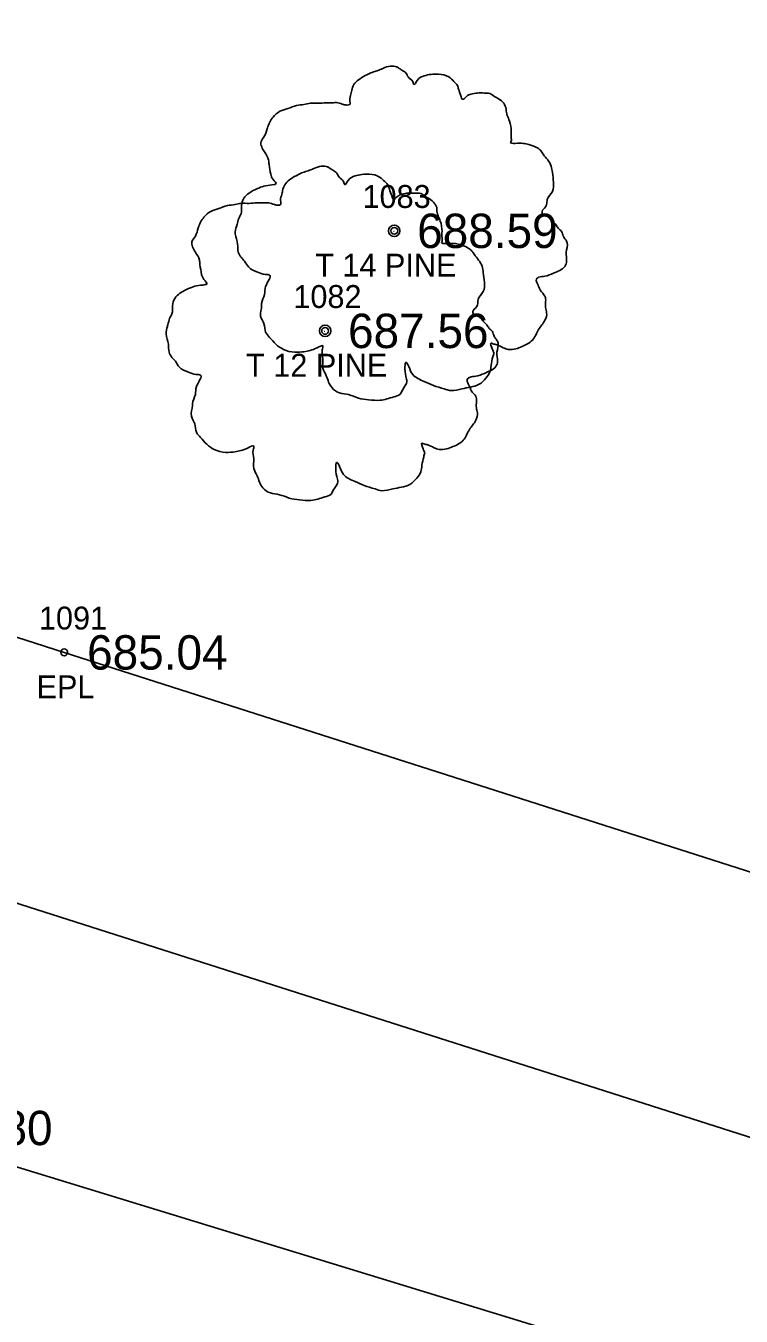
# Model space of a CAD drawing. Extents: x 1655137 to 1657928, y 1003994 to 1005407.
# Drawn here: x 1656964.1 to 1656995.4, y 1004411.6 to 1004468 of the extents above; entities that cross this region are included whole.
import ezdxf

# ---------------------------------------------------------------- set-up
doc = ezdxf.new("R2010")
doc.units = 0
for name, color, linetype in [('RD_EX_Road', 7, 'Continuous'), ('RD_EX_Road_txCode', 7, 'Continuous'), ('RD_EX_TX_Road_ELEV', 7, 'Continuous'), ('RD_EX_TX_VEG_ELEV', 7, 'Continuous'), ('RD_EX_VEG', 7, 'Continuous'), ('RD_EX_VEG_txCode', 7, 'Continuous'), ('RD_HC_Cl', 7, 'Continuous'), ('RD_SMD_Locator', 7, 'Continuous')]:
    doc.layers.add(name, color=color, linetype=linetype)

msp = doc.modelspace()

# ---------------------------------------------------------------- linework, layer by layer
at = {"layer": 'RD_EX_Road'}
for points in [[(1657064.386, 1004409.093), (1657015.673, 1004424.638), (1656965.82, 1004440.601), (1656917.987, 1004455.951), (1656868.502, 1004471.858), (1656826.533, 1004486.061), (1656801.74, 1004494.508), (1656772.14, 1004504.273), (1656723.449, 1004520.924), (1656674.937, 1004537.34), (1656626.5, 1004553.879), (1656578.266, 1004569.524), (1656529.181, 1004584.752), (1656481.495, 1004600.509), (1656432.674, 1004617.136), (1656404.342, 1004625.816)], [(1657057.771, 1004388.922), (1657009.7, 1004404.075), (1656958.177, 1004419.835), (1656956.487, 1004419.667), (1656924.827, 1004429.547), (1656916.506, 1004432.799), (1656911.189, 1004434.68), (1656862.464, 1004450.207), (1656813.53, 1004466.421), (1656765.511, 1004482.334), (1656716.805, 1004499.141), (1656668.597, 1004515.926), (1656620.24, 1004532.541), (1656571.717, 1004548.369), (1656523.305, 1004563.773), (1656474.365, 1004580.294), (1656426.433, 1004596.82), (1656398.222, 1004606.78)]]:
    msp.add_lwpolyline(points, dxfattribs=at)
at = {"layer": 'RD_EX_VEG'}
for centre, radius in [((1656980.233, 1004459.009), 0.25), ((1656980.22, 1004458.99), 0.0001), ((1656977.214, 1004454.64), 0.25), ((1656977.201, 1004454.621), 0.0001)]:
    msp.add_circle(centre, radius, dxfattribs=at)
for points in [[(1656980.365, 1004466.176), (1656980.065, 1004466.201), (1656979.74, 1004466.101), (1656979.49, 1004466.002), (1656979.265, 1004465.927), (1656979.04, 1004465.827), (1656978.74, 1004465.652), (1656978.515, 1004465.452), (1656978.39, 1004465.202), (1656978.34, 1004464.977), (1656978.29, 1004464.702), (1656978.29, 1004464.527), (1656978.166, 1004464.502), (1656978.016, 1004464.527), (1656977.766, 1004464.602), (1656977.516, 1004464.602), (1656977.266, 1004464.602), (1656976.916, 1004464.577), (1656976.566, 1004464.577), (1656976.291, 1004464.527), (1656975.966, 1004464.477), (1656975.592, 1004464.352), (1656975.242, 1004464.227), (1656974.942, 1004463.977), (1656974.692, 1004463.503), (1656974.567, 1004463.153), (1656974.417, 1004462.903), (1656974.567, 1004462.453), (1656974.742, 1004462.103), (1656974.767, 1004461.903), (1656974.842, 1004461.479), (1656974.942, 1004461.254), (1656975.067, 1004461.054), (1656974.992, 1004461.029), (1656974.617, 1004460.979), (1656974.317, 1004460.879), (1656973.892, 1004460.654), (1656973.667, 1004460.429), (1656973.567, 1004460.104), (1656973.543, 1004459.754), (1656973.443, 1004459.554), (1656973.368, 1004459.279), (1656973.343, 1004459.204), (1656973.293, 1004458.88), (1656973.393, 1004458.43), (1656973.418, 1004458.08), (1656973.543, 1004457.855), (1656973.692, 1004457.68), (1656973.867, 1004457.43), (1656974.267, 1004457.205), (1656974.592, 1004457.105), (1656974.792, 1004457.08), (1656974.617, 1004456.581), (1656974.567, 1004456.231), (1656974.442, 1004455.831), (1656974.442, 1004455.756), (1656974.392, 1004455.281), (1656974.542, 1004454.956), (1656974.617, 1004454.582), (1656974.792, 1004454.357), (1656975.067, 1004454.057), (1656975.392, 1004453.832), (1656975.892, 1004453.707), (1656976.291, 1004453.732), (1656976.866, 1004453.907), (1656977.116, 1004453.982), (1656977.091, 1004453.807), (1656977.116, 1004453.432), (1656977.116, 1004453.007), (1656977.266, 1004452.682), (1656977.366, 1004452.407), (1656977.516, 1004452.158), (1656977.841, 1004451.933), (1656978.24, 1004451.858), (1656978.665, 1004451.708), (1656979.115, 1004451.633), (1656979.615, 1004451.608), (1656980.215, 1004451.758), (1656980.489, 1004451.883), (1656980.589, 1004452.058), (1656980.789, 1004452.432), (1656980.739, 1004452.657), (1656980.764, 1004453.257), (1656980.864, 1004453.082), (1656981.039, 1004452.732), (1656981.539, 1004452.432), (1656981.939, 1004452.258), (1656982.414, 1004452.108), (1656982.714, 1004452.033), (1656983.188, 1004452.108), (1656983.563, 1004452.183), (1656983.938, 1004452.308), (1656984.238, 1004452.582), (1656984.413, 1004452.857), (1656984.463, 1004453.132), (1656984.538, 1004453.507), (1656984.588, 1004453.682)], [(1656984.588, 1004453.682), (1656984.513, 1004453.857), (1656984.463, 1004454.107), (1656984.538, 1004454.082), (1656984.713, 1004454.032), (1656984.988, 1004453.907), (1656985.212, 1004453.832), (1656985.537, 1004453.857), (1656985.812, 1004453.957), (1656986.262, 1004454.232), (1656986.537, 1004454.706), (1656986.812, 1004455.106), (1656986.887, 1004455.431), (1656986.837, 1004455.656), (1656986.812, 1004456.156), (1656986.612, 1004456.406), (1656986.562, 1004456.531), (1656986.462, 1004456.93), (1656986.537, 1004456.98), (1656986.812, 1004457.03), (1656987.187, 1004457.155), (1656987.461, 1004457.28), (1656987.686, 1004457.455), (1656987.761, 1004457.68), (1656987.736, 1004458.08), (1656987.786, 1004458.48), (1656987.711, 1004458.63), (1656987.611, 1004458.78), (1656987.536, 1004458.98), (1656987.386, 1004459.129), (1656987.287, 1004459.279), (1656987.187, 1004459.379), (1656987.062, 1004459.529), (1656986.887, 1004459.654), (1656986.737, 1004459.704), (1656986.687, 1004459.854), (1656986.837, 1004460.054), (1656986.887, 1004460.154), (1656986.912, 1004460.379), (1656987.137, 1004460.729), (1656987.187, 1004461.129), (1656987.137, 1004461.553), (1656987.087, 1004461.828), (1656986.937, 1004462.103), (1656986.737, 1004462.353), (1656986.612, 1004462.528), (1656986.437, 1004462.653), (1656986.112, 1004462.778), (1656985.862, 1004462.828), (1656985.512, 1004462.828), (1656985.312, 1004462.878), (1656985.337, 1004462.928), (1656985.337, 1004463.078), (1656985.337, 1004463.353), (1656985.262, 1004463.802), (1656985.112, 1004464.302), (1656985.112, 1004464.327), (1656985.012, 1004464.577), (1656984.788, 1004464.777), (1656984.613, 1004464.877), (1656984.413, 1004465.002), (1656984.163, 1004465.027), (1656983.863, 1004465.027), (1656983.588, 1004464.977), (1656983.388, 1004464.877), (1656983.213, 1004464.752), (1656983.138, 1004464.902), (1656983.038, 1004465.202), (1656982.988, 1004465.352), (1656982.838, 1004465.527), (1656982.614, 1004465.727), (1656982.164, 1004465.852), (1656981.539, 1004465.777), (1656981.239, 1004465.577), (1656981.089, 1004465.402), (1656981.039, 1004465.527), (1656980.839, 1004465.727), (1656980.739, 1004465.902), (1656980.564, 1004466.027), (1656980.415, 1004466.126), (1656980.315, 1004466.176)], [(1656977.346, 1004461.807), (1656977.046, 1004461.832), (1656976.721, 1004461.732), (1656976.471, 1004461.632), (1656976.246, 1004461.557), (1656976.021, 1004461.457), (1656975.722, 1004461.282), (1656975.497, 1004461.082), (1656975.372, 1004460.832), (1656975.322, 1004460.607), (1656975.272, 1004460.333), (1656975.272, 1004460.158), (1656975.147, 1004460.133), (1656974.997, 1004460.158), (1656974.747, 1004460.233), (1656974.497, 1004460.233), (1656974.247, 1004460.233), (1656973.897, 1004460.208), (1656973.547, 1004460.208), (1656973.273, 1004460.158), (1656972.948, 1004460.108), (1656972.573, 1004459.983), (1656972.223, 1004459.858), (1656971.923, 1004459.608), (1656971.673, 1004459.133), (1656971.548, 1004458.783), (1656971.398, 1004458.533), (1656971.548, 1004458.084), (1656971.723, 1004457.734), (1656971.748, 1004457.534), (1656971.823, 1004457.109), (1656971.923, 1004456.884), (1656972.048, 1004456.684), (1656971.973, 1004456.659), (1656971.598, 1004456.609), (1656971.298, 1004456.509), (1656970.874, 1004456.284), (1656970.649, 1004456.059), (1656970.549, 1004455.734), (1656970.524, 1004455.385), (1656970.424, 1004455.185), (1656970.349, 1004454.91), (1656970.324, 1004454.835), (1656970.274, 1004454.51), (1656970.374, 1004454.06), (1656970.399, 1004453.71), (1656970.524, 1004453.485), (1656970.674, 1004453.311), (1656970.849, 1004453.061), (1656971.248, 1004452.836), (1656971.573, 1004452.736), (1656971.773, 1004452.711), (1656971.598, 1004452.211), (1656971.548, 1004451.861), (1656971.423, 1004451.461), (1656971.423, 1004451.386), (1656971.373, 1004450.912), (1656971.523, 1004450.587), (1656971.598, 1004450.212), (1656971.773, 1004449.987), (1656972.048, 1004449.687), (1656972.373, 1004449.462), (1656972.873, 1004449.337), (1656973.273, 1004449.362), (1656973.847, 1004449.537), (1656974.097, 1004449.612), (1656974.072, 1004449.437), (1656974.097, 1004449.062), (1656974.097, 1004448.638), (1656974.247, 1004448.313), (1656974.347, 1004448.038), (1656974.497, 1004447.788), (1656974.822, 1004447.563), (1656975.222, 1004447.488), (1656975.647, 1004447.338), (1656976.096, 1004447.263), (1656976.596, 1004447.238), (1656977.196, 1004447.388), (1656977.471, 1004447.513), (1656977.571, 1004447.688), (1656977.771, 1004448.063), (1656977.721, 1004448.288), (1656977.746, 1004448.888), (1656977.846, 1004448.713), (1656978.021, 1004448.363), (1656978.52, 1004448.063), (1656978.92, 1004447.888), (1656979.395, 1004447.738), (1656979.695, 1004447.663), (1656980.17, 1004447.738), (1656980.544, 1004447.813), (1656980.919, 1004447.938), (1656981.219, 1004448.213), (1656981.394, 1004448.488), (1656981.444, 1004448.763), (1656981.519, 1004449.137), (1656981.569, 1004449.312)], [(1656981.569, 1004449.312), (1656981.494, 1004449.487), (1656981.444, 1004449.737), (1656981.519, 1004449.712), (1656981.694, 1004449.662), (1656981.969, 1004449.537), (1656982.194, 1004449.462), (1656982.519, 1004449.487), (1656982.793, 1004449.587), (1656983.243, 1004449.862), (1656983.518, 1004450.337), (1656983.793, 1004450.737), (1656983.868, 1004451.062), (1656983.818, 1004451.286), (1656983.793, 1004451.786), (1656983.593, 1004452.036), (1656983.543, 1004452.161), (1656983.443, 1004452.561), (1656983.518, 1004452.611), (1656983.793, 1004452.661), (1656984.168, 1004452.786), (1656984.443, 1004452.911), (1656984.668, 1004453.086), (1656984.743, 1004453.311), (1656984.718, 1004453.71), (1656984.768, 1004454.11), (1656984.693, 1004454.26), (1656984.593, 1004454.41), (1656984.518, 1004454.61), (1656984.368, 1004454.76), (1656984.268, 1004454.91), (1656984.168, 1004455.01), (1656984.043, 1004455.16), (1656983.868, 1004455.285), (1656983.718, 1004455.335), (1656983.668, 1004455.485), (1656983.818, 1004455.685), (1656983.868, 1004455.784), (1656983.893, 1004456.009), (1656984.118, 1004456.359), (1656984.168, 1004456.759), (1656984.118, 1004457.184), (1656984.068, 1004457.459), (1656983.918, 1004457.734), (1656983.718, 1004457.984), (1656983.593, 1004458.158), (1656983.418, 1004458.283), (1656983.093, 1004458.408), (1656982.843, 1004458.458), (1656982.494, 1004458.458), (1656982.294, 1004458.508), (1656982.319, 1004458.558), (1656982.319, 1004458.708), (1656982.319, 1004458.983), (1656982.244, 1004459.433), (1656982.094, 1004459.933), (1656982.094, 1004459.958), (1656981.994, 1004460.208), (1656981.769, 1004460.407), (1656981.594, 1004460.507), (1656981.394, 1004460.632), (1656981.144, 1004460.657), (1656980.844, 1004460.657), (1656980.569, 1004460.607), (1656980.369, 1004460.507), (1656980.195, 1004460.382), (1656980.12, 1004460.532), (1656980.02, 1004460.832), (1656979.97, 1004460.982), (1656979.82, 1004461.157), (1656979.595, 1004461.357), (1656979.145, 1004461.482), (1656978.52, 1004461.407), (1656978.22, 1004461.207), (1656978.07, 1004461.032), (1656978.021, 1004461.157), (1656977.821, 1004461.357), (1656977.721, 1004461.532), (1656977.546, 1004461.657), (1656977.396, 1004461.757), (1656977.296, 1004461.807)]]:
    msp.add_spline(points, degree=3, dxfattribs=at)
at = {"layer": 'RD_HC_Cl'}
msp.add_line((1656857.937, 1004463.429), (1657009.055, 1004415.181), dxfattribs=at)
at = {"layer": 'RD_SMD_Locator'}
for centre in [(1656980.233, 1004459.009), (1656977.214, 1004454.64), (1656965.82, 1004440.601)]:
    msp.add_circle(centre, 0.15, dxfattribs=at)

# ---------------------------------------------------------------- texts
at = {"layer": 'RD_EX_Road_txCode'}
for s, p in [('1091', (1656964.718, 1004441.601)), ('EPL', (1656964.615, 1004438.601))]:
    msp.add_text(s, height=1, dxfattribs=at).set_placement(p)
at = {"layer": 'RD_EX_TX_Road_ELEV'}
for s, p in [('685.04', (1656966.82, 1004439.851)), ('685.80', (1656959.177, 1004419.085))]:
    msp.add_text(s, height=1.5, dxfattribs=at).set_placement(p)
at = {"layer": 'RD_EX_TX_VEG_ELEV'}
for s, p in [('688.59', (1656981.233, 1004458.259)), ('687.56', (1656978.214, 1004453.89))]:
    msp.add_text(s, height=1.5, dxfattribs=at).set_placement(p)
at = {"layer": 'RD_EX_VEG_txCode'}
for s, p in [('1083', (1656978.847, 1004460.009)), ('T 14 PINE', (1656976.78, 1004457.009)), ('1082', (1656975.828, 1004455.64)), ('T 12 PINE', (1656973.761, 1004452.64))]:
    msp.add_text(s, height=1, dxfattribs=at).set_placement(p)

doc.saveas('drawing.dxf')
